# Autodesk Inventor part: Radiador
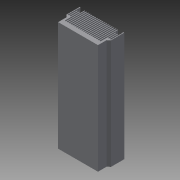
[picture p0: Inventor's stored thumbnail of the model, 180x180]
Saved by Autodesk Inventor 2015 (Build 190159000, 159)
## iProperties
Created: 2016-04
Part Number: Radiador
Material: Genérico
Document SubType Name: Modeling
Designer: Diego
Density: 1 g/cm^3
Appearance: Valor por defecto
Author: Diego
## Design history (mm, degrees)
sketch "Boceto1"
  geometry: L1 (-3.5, 36)-(-3.5, 16); L2 (0, 13)-(-3.5, 16); L3 (3, 7)-(3, 17); L4 (3, 17)-(3, 29); L5 (2, 29)-(2, 17); L6 (-3.5, 36)-(-2.5, 36); L7 (-0.75, 29)-(-0.75, 17); L8 (0.25, 29)-(0.25, 17); L9 (-2.5, 17)-(-0.75, 17); L10 (0.25, 17)-(2, 17); L11 (-2.5, 36)-(-1.625, 34.905); L12 (-1.625, 34.905)-(-2.5, 34.905); L13 (-2.5, 17)-(-2.5, 34.905); L14 (3, 7)-(4.75, 7); L15 (4.75, 35)-(4.75, 7); L16 (4.75, 35)-(4.75, 7); L17 (3, 7)-(4.75, 7); L18 (0, 0)-(0, 13); L19 (0, 13)-(-3.5, 16); L20 (-3.5, 16)-(-3.5, 36); L21 (3, 7)-(4.75, 7); L22 (3, 7)-(3, 17); L23 (4.75, 35)-(5.75, 35); L24 (5.75, 35)-(5.75, 7); L25 (5.75, 7)-(7.5, 7); L26 (7.5, 7)-(7.5, 35); L27 (7.5, 35)-(8.5, 35); L28 (8.5, 35)-(8.5, 7); L29 (8.5, 7)-(10.25, 7); L30 (10.25, 7)-(10.25, 35); L31 (10.25, 35)-(11.25, 35); L32 (11.25, 35)-(11.25, 7); L33 (11.25, 7)-(13, 7); L34 (13, 7)-(13, 35); L35 (13, 35)-(14, 35); L36 (14, 35)-(14, 7); L37 (14, 7)-(15.75, 7); L38 (15.75, 7)-(15.75, 35); L39 (15.75, 35)-(16.75, 35); L40 (16.75, 35)-(16.75, 7); L41 (16.75, 7)-(18.5, 7); L42 (18.5, 7)-(18.5, 35); L43 (18.5, 35)-(19.5, 35); L44 (19.5, 35)-(19.5, 7); L45 (19.5, 7)-(21.25, 7); L46 (21.25, 7)-(21.25, 35); L47 (21.25, 35)-(22.25, 35); L48 (22.25, 35)-(22.25, 7); L49 (22.25, 7)-(24, 7); L50 (24, 7)-(24, 35); L51 (24, 35)-(25, 35); L52 (25, 35)-(25, 7); L53 (25, 7)-(26.75, 7); L54 (26.75, 7)-(26.75, 35); L55 (26.75, 35)-(27.75, 35); L56 (27.75, 35)-(27.75, 7); L57 (27.75, 7)-(29.5, 7); L58 (29.5, 7)-(29.5, 35); L59 (29.5, 35)-(30.5, 35); L60 (30.5, 35)-(30.5, 7); L61 (30.5, 7)-(30.5, 0); L62 (30.5, 0)-(0, 0); L63 (30, 35)-(30, 13); L64 (52.5, 35)-(51.5, 35)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; A1 r 0.5 centre (-0.25, 29) between (0.25, 29) and (-0.75, 29); A2 r 0.5 centre (2.5, 29) between (3, 29) and (2, 29); A3 r 0.5 centre (60.25, 29) between (60.75, 29) and (59.75, 29); A4 r 0.5 centre (57.5, 29) between (58, 29) and (57, 29)
  constraints: 250 end point, 64 symmetric about line, 36 point on line, 13 perpendicular, 8 point on circle, 6 horizontal, 4 centre point, 3 parallel, 1 midpoint, 1 vertical, 2 other
extrude "Extrusión1" new body sketch "Boceto1" distance "d88" = 165; taper "d89" = 0 deg
node "Sólido1"
